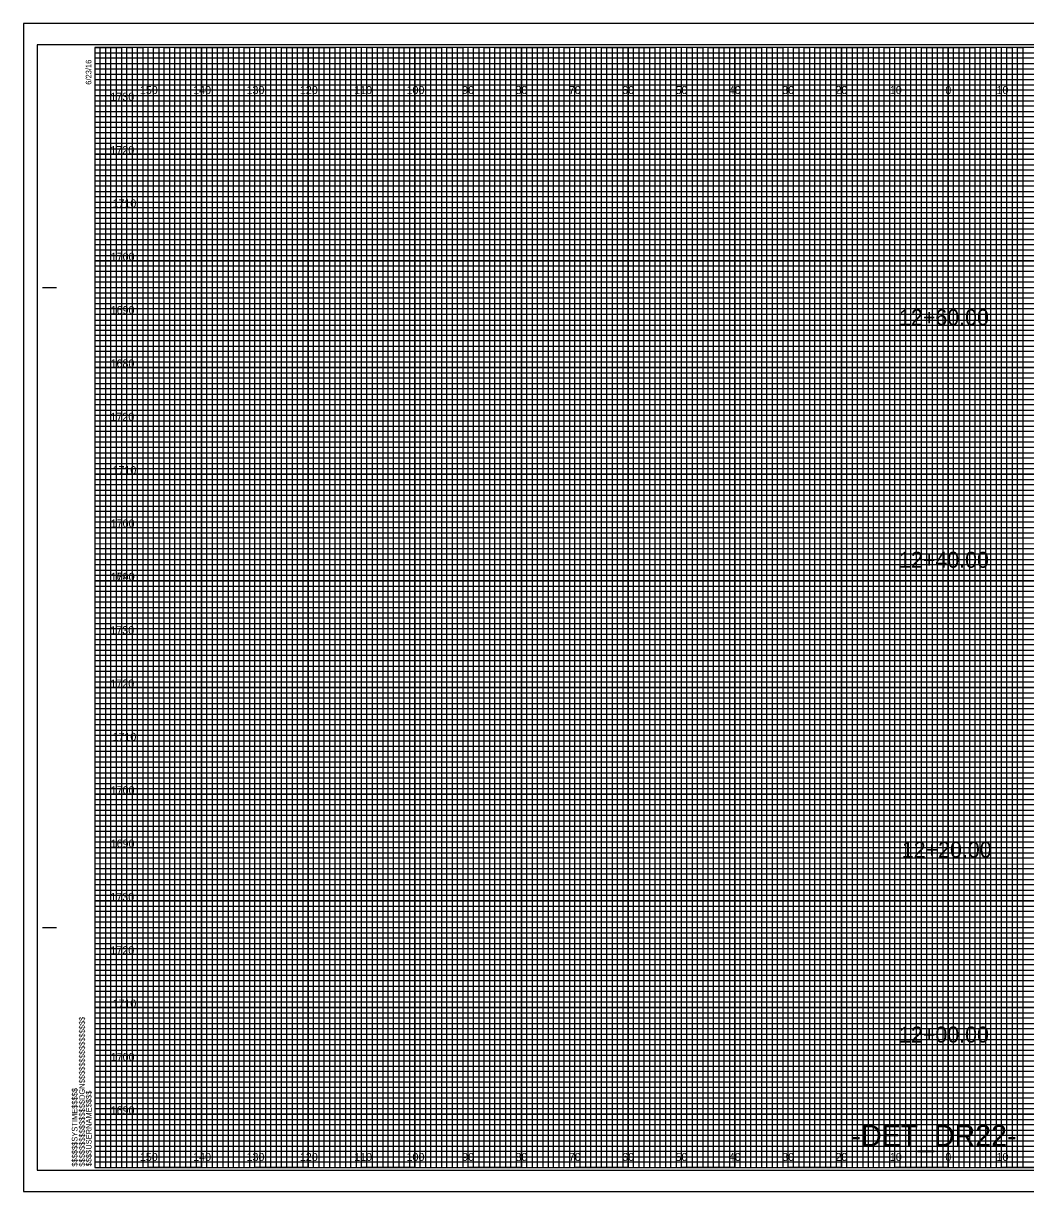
# Model space of a CAD drawing. Extents: x -13 to 323, y -5 to 1314.
# Drawn here: x -13.4 to 174.5, y 435.5 to 654.5 of the extents above; entities that cross this region are included whole.
import ezdxf

# ---------------------------------------------------------------- set-up
doc = ezdxf.new("R2010")
doc.units = 0
for name, color, linetype in [('Prop Horizontal Alignment', 7, 'Continuous'), ('Prop XS Alignment Label', 7, 'Continuous'), ('Raster_Level_0', 7, 'Continuous'), ('Scratch_Level_3', 7, 'Continuous'), ('Sheet Cross Section CELL', 7, 'Continuous'), ('Sheet Cross Section Grid Major CELL', 7, 'Continuous'), ('Sheet Cross Section Grid Middle CELL', 7, 'Continuous'), ('Sheet Cross Section Grid Minor 1 CELL', 7, 'Continuous'), ('Sheet Cross Section Grid Minor 2 CELL', 7, 'Continuous'), ('Sheet Cutting Line CELL', 7, 'Continuous'), ('Sheet DOT Grid CELL', 7, 'Continuous'), ('Sheet Plot Border Inside CELL', 7, 'Continuous'), ('Sheet Plot Border Outside CELL', 7, 'Continuous')]:
    doc.layers.add(name, color=color, linetype=linetype)

msp = doc.modelspace()

# ---------------------------------------------------------------- linework, layer by layer
at = {"layer": 'Sheet Cross Section CELL'}
for p, q in [((-9.8, 605), (-7.3, 605)), ((-9.7, 605), (-7.2, 605)), ((-9.8, 485), (-7.3, 485)), ((-9.7, 485), (-7.2, 485)), ((0, 440), (0, 440)), ((0, 440), (0, 440)), ((0, 440), (0, 440)), ((0, 440), (0, 440)), ((0, 440), (0, 440)), ((0, 440), (0, 440)), ((0, 440), (0, 440))]:
    msp.add_line(p, q, dxfattribs=at)
msp.add_lwpolyline([(320, 650), (0, 650), (0, 440), (320, 440)], close=True, dxfattribs=at)
at = {"layer": 'Sheet Cross Section Grid Major CELL'}
for p, q in [((10, 650), (0, 650)), ((10, 440), (10, 650)), ((30, 650), (20, 650)), ((20, 650), (20, 440)), ((30, 440), (30, 650)), ((50, 650), (40, 650)), ((40, 650), (40, 440)), ((50, 440), (50, 650)), ((70, 650), (60, 650)), ((60, 650), (60, 440)), ((70, 440), (70, 650)), ((90, 650), (80, 650)), ((80, 650), (80, 440)), ((90, 440), (90, 650)), ((110, 650), (100, 650)), ((100, 650), (100, 440)), ((110, 440), (110, 650)), ((130, 650), (120, 650)), ((120, 650), (120, 440)), ((130, 440), (130, 650)), ((150, 650), (140, 650)), ((140, 650), (140, 440)), ((150, 440), (150, 650)), ((170, 650), (160, 650)), ((160, 650), (160, 440)), ((170, 440), (170, 650)), ((20, 440), (10, 440)), ((40, 440), (30, 440)), ((60, 440), (50, 440)), ((80, 440), (70, 440)), ((100, 440), (90, 440)), ((120, 440), (110, 440)), ((140, 440), (130, 440)), ((160, 440), (150, 440)), ((180, 440), (170, 440))]:
    msp.add_line(p, q, dxfattribs=at)
for points in [[(0, 640), (320, 640), (320, 630), (0, 630)], [(0, 620), (320, 620), (320, 610), (0, 610)], [(0, 600), (320, 600), (320, 590), (0, 590)], [(0, 580), (320, 580), (320, 570), (0, 570)], [(0, 560), (320, 560), (320, 550), (0, 550)], [(0, 540), (320, 540), (320, 530), (0, 530)], [(0, 520), (320, 520), (320, 510), (0, 510)], [(0, 500), (320, 500), (320, 490), (0, 490)], [(0, 480), (320, 480), (320, 470), (0, 470)], [(0, 460), (320, 460), (320, 450), (0, 450)]]:
    msp.add_lwpolyline(points, dxfattribs=at)
at = {"layer": 'Sheet Cross Section Grid Middle CELL'}
for points in [[(0, 650), (5, 650), (5, 440), (15, 440), (15, 650), (25, 650), (25, 440), (35, 440), (35, 650), (45, 650), (45, 440), (55, 440), (55, 650), (65, 650), (65, 440), (75, 440), (75, 650), (85, 650), (85, 440), (95, 440), (95, 650), (105, 650), (105, 440), (115, 440), (115, 650), (125, 650), (125, 440), (135, 440), (135, 650), (145, 650), (145, 440), (155, 440), (155, 650), (165, 650), (165, 440), (175, 440)], [(0, 645), (275, 645)], [(0, 625), (320, 625), (320, 635), (0, 635)], [(0, 605), (320, 605), (320, 615), (0, 615)], [(0, 585), (320, 585), (320, 595), (0, 595)], [(0, 565), (320, 565), (320, 575), (0, 575)], [(0, 545), (320, 545), (320, 555), (0, 555)], [(0, 525), (320, 525), (320, 535), (0, 535)], [(0, 505), (320, 505), (320, 515), (0, 515)], [(0, 485), (320, 485), (320, 495), (0, 495)], [(0, 465), (320, 465), (320, 475), (0, 475)], [(0, 445), (320, 445), (320, 455), (0, 455)]]:
    msp.add_lwpolyline(points, dxfattribs=at)
at = {"layer": 'Sheet Cross Section Grid Minor 1 CELL'}
for p, q in [((0, 649), (260, 649)), ((260, 647.98), (0, 647.98)), ((0, 647.98), (0, 647)), ((0, 647), (260, 647)), ((260, 645.89), (0, 645.89)), ((0, 645.89), (0, 644)), ((0, 644), (320, 644))]:
    msp.add_line(p, q, dxfattribs=at)
for points in [[(0, 643), (270, 643), (320, 643), (320, 642), (0, 642)], [(0, 641), (320, 641), (320, 639), (0, 639)], [(0, 638), (320, 638), (320, 637), (0, 636.98)], [(0, 636), (320, 636), (320, 634), (0, 634)], [(0, 633), (320, 633), (320, 632), (0, 632)], [(0, 631), (320, 631), (320, 629), (0, 629)], [(0, 628), (320, 628), (320, 627), (0, 627)], [(0, 626), (320, 626), (320, 624), (0, 624)], [(0, 623), (320, 623), (320, 622), (0, 622)], [(0, 621), (320, 621), (320, 619), (0, 619)], [(0, 618), (320, 618), (320, 617), (0, 617)], [(0, 616), (320, 616), (320, 613.95), (320, 613), (320, 612), (0, 612)], [(0, 614), (320, 614), (320, 613), (0, 613)], [(0, 611), (320, 611), (320, 609), (0, 609.03)], [(0, 609.03), (320, 609), (320, 608), (0, 608)], [(0, 607), (320, 607), (320, 606), (0, 606)], [(0, 604), (320, 604), (320, 603), (0, 603)], [(0, 602), (320, 602), (320, 601), (0, 601)], [(-0.07, 598.89), (320, 598.89), (320, 597.88), (-0.07, 597.88)], [(0, 597), (320, 597), (320, 596), (0, 596)], [(0, 594), (320, 594), (320, 593), (0, 593)], [(0, 592), (320, 592), (320, 591), (0, 591)], [(0, 589), (320, 589), (320, 588), (0, 588)], [(0, 587), (320, 587), (320, 586), (0, 586)], [(0, 584), (320, 584), (320, 583), (0, 583)], [(0, 582), (320, 582), (320, 581), (0, 581)], [(0, 579), (320, 579), (319.99, 577.98), (0, 578)], [(0, 577), (320, 577), (320, 576), (0, 576)], [(0, 574), (320, 574), (320, 573), (0, 573)], [(0, 572), (320, 572), (320, 571), (0, 571)], [(0, 569), (320, 569), (320, 568), (0, 568)], [(0, 567), (320, 567), (320, 566), (0, 566)], [(0, 564), (320, 564), (320, 563), (0, 563)], [(0, 562), (320, 562), (320, 561), (0, 561)], [(0, 559), (320, 559), (320, 558), (0, 558)], [(0, 556.99), (320.07, 556.91), (320, 556), (0, 556)], [(0, 554), (320, 554), (320, 553), (0, 553)], [(0, 552), (320, 552), (320, 551), (0, 551)], [(0, 549), (320, 549), (320, 548), (0, 548)], [(0, 547), (320, 547), (320, 546), (0, 546)], [(0, 544), (320, 544), (320, 543), (0, 543)], [(0, 542), (320, 542), (320, 541), (0, 541)], [(0, 539), (320, 539), (320, 538), (0, 538)], [(0, 537), (320, 537), (320, 536), (0, 536)], [(0, 534), (320, 534), (320, 533), (0, 533)], [(0, 532), (320, 532), (320, 531), (0, 531)], [(0, 529), (320, 529), (320, 528), (0, 528)], [(0, 527), (320, 527), (320, 526), (0, 526)], [(0, 524), (320, 524), (320, 523), (0, 523)], [(0, 522), (320, 522), (320, 521), (0, 521)], [(0, 519), (320, 519), (319.99, 517.98), (0, 518)], [(0, 517), (320, 517), (320, 516), (0, 516)], [(0, 514), (320, 514), (320, 513), (0, 513)], [(0, 512), (320, 512), (320, 511), (0, 511)], [(0, 509), (320, 509), (320, 508), (0, 508)], [(0, 507), (320, 507), (320, 506), (0, 506)], [(0, 504), (320, 504), (320, 503), (0, 503)], [(0, 502), (320, 502), (320, 501), (0, 501)], [(0, 499), (320, 499), (320, 498), (0, 498)], [(0, 496.99), (320.07, 496.91), (320, 496), (0, 496)], [(0, 494), (320, 494), (320, 493), (0, 493)], [(0, 492), (320, 492), (320, 491), (0, 491)], [(0, 489), (320, 489), (320, 488), (0, 488)], [(0, 487), (320, 487), (320, 486), (0, 486)], [(0, 484), (320, 484), (320, 483), (0, 483)], [(0, 482), (320, 482), (320, 481), (0, 481)], [(0, 479), (320, 479), (320, 478), (0, 478)], [(0, 477), (320, 477), (320, 476), (0, 476)], [(0, 474), (320, 474), (320, 473), (0, 473)], [(0, 472), (320, 472), (320, 471), (0, 471)], [(0, 469), (320, 469), (320, 468), (0, 468)], [(0, 467), (320, 467), (320, 466), (0, 466)], [(0, 464), (320, 464), (320, 463), (0, 463)], [(0, 462), (320, 462), (320, 461), (0, 461)], [(0, 459), (320, 459), (320, 458), (0, 458)], [(0, 457), (320, 457), (320, 456), (0, 456)], [(0, 454), (320, 454), (320, 453), (0, 453)], [(0, 452), (320, 452), (320, 451), (0, 451)], [(0, 449), (320, 449), (320, 448), (0, 448)], [(0, 447), (320, 447), (320, 446), (0, 446)], [(0, 444), (320, 444), (320, 443), (0, 443)], [(0, 442), (320, 442), (320, 441), (0, 441)]]:
    msp.add_lwpolyline(points, dxfattribs=at)
at = {"layer": 'Sheet Cross Section Grid Minor 2 CELL'}
for points in [[(0, 440), (1, 440), (1, 650), (2, 650), (2, 440)], [(2, 440), (3, 440), (3, 650), (4, 650), (4, 440)], [(5, 440), (6, 440), (6, 650), (7, 650), (7, 440)], [(7, 440), (8, 440), (8, 650), (9, 650), (9, 440)], [(10, 440), (11, 440), (11, 650), (12, 650), (12, 440)], [(12, 440), (13, 440), (13, 650), (14, 650), (14, 440)], [(15, 440), (16, 440), (16, 650), (17, 650), (17, 440)], [(17, 440), (18, 440), (18, 650), (19, 650), (19, 440)], [(20, 440), (21, 440), (21, 650), (22, 650), (22, 440)], [(22, 440), (23, 440), (23, 650), (24, 650), (24, 440)], [(25, 440), (26, 440), (26, 650), (27, 650), (27, 440)], [(27, 440), (28, 440), (28, 650), (29, 650), (29, 440)], [(30, 440), (31, 440), (31, 650), (32, 650), (32, 440)], [(32, 440), (33, 440), (33, 650), (34, 650), (34, 440)], [(35, 440), (36, 440), (36, 650), (37, 650), (37, 440)], [(37, 440), (38, 440), (38, 650), (39, 650), (39, 440)], [(40, 440), (41, 440), (41, 650), (42, 650), (42, 440)], [(42, 440), (43, 440), (43, 650), (44, 650), (44, 440)], [(45, 440), (46, 440), (46, 650), (47, 650), (47, 440)], [(47, 440), (48, 440), (48, 650), (49, 650), (49, 440)], [(50, 440), (51, 440), (51, 650), (52, 650), (52, 440)], [(52, 440), (53, 440), (53, 650), (54, 650), (54, 440)], [(55, 440), (56, 440), (56, 650), (57, 650), (57, 440)], [(57, 440), (58, 440), (58, 650), (59, 650), (59, 440)], [(60, 440), (61, 440), (61, 650), (62, 650), (62, 440)], [(62, 440), (63, 440), (63, 650), (64, 650), (64, 440)], [(65, 440), (66, 440), (66, 650), (67, 650), (67, 440)], [(67, 440), (68, 440), (68, 650), (69, 650), (69, 440)], [(70, 440), (71, 440), (71, 650), (72, 650), (72, 440)], [(72, 440), (73, 440), (73, 650), (74, 650), (74, 440)], [(75, 440), (76, 440), (76, 650), (77, 650), (77, 440)], [(77, 440), (78, 440), (78, 650), (79, 650), (79, 440)], [(80, 440), (81, 440), (81, 650), (82, 650), (82, 440)], [(82, 440), (83, 440), (83, 650), (84, 650), (84, 440)], [(85, 440), (86, 440), (86, 650), (87, 650), (87, 440)], [(87, 440), (88, 440), (88, 650), (89, 650), (89, 440)], [(90, 440), (91, 440), (91, 650), (92, 650), (92, 440)], [(92, 440), (93, 440), (93, 650), (94, 650), (94, 440)], [(95, 440), (96, 440), (96, 650), (97, 650), (97, 440)], [(97, 440), (98, 440), (98, 650), (99, 650), (99, 440)], [(100, 440), (101, 440), (101, 650), (102, 650), (102, 440)], [(102, 440), (103, 440), (103, 650), (104, 650), (104, 440)], [(105, 440), (106, 440), (106, 650), (107, 650), (107, 440)], [(107, 440), (108, 440), (108, 650), (109, 650), (109, 440)], [(110, 440), (111, 440), (111, 650), (112, 650), (112, 440)], [(112, 440), (113, 440), (113, 650), (114, 650), (114, 440)], [(115, 440), (116, 440), (116, 650), (117, 650), (117, 440)], [(117, 440), (118, 440), (118, 650), (119, 650), (119, 440)], [(120, 440), (121, 440), (121, 650), (122, 650), (122, 440)], [(122, 440), (123, 440), (123, 650), (124, 650), (124, 440)], [(125, 440), (126, 440), (126, 650), (127, 650), (127, 440)], [(127, 440), (128, 440), (128, 650), (129, 650), (129, 440)], [(130, 440), (131, 440), (131, 650), (132, 650), (132, 440)], [(132, 440), (133, 440), (133, 650), (134, 650), (134, 440)], [(135, 440), (136, 440), (136, 650), (137, 650), (137, 440)], [(137, 440), (138, 440), (138, 650), (139, 650), (139, 440)], [(140, 440), (141, 440), (141, 650), (142, 650), (142, 440)], [(142, 440), (143, 440), (143, 650), (144, 650), (144, 440)], [(145, 440), (146, 440), (146, 650), (147, 650), (147, 440)], [(147, 440), (148, 440), (148, 650), (149, 650), (149, 440)], [(150, 440), (151, 440), (151, 650), (152, 650), (152, 440)], [(152, 440), (153, 440), (153, 650), (154, 650), (154, 440)], [(155, 440), (156, 440), (156, 650), (157, 650), (157, 440)], [(157, 440), (158, 440), (158, 650), (159, 650), (159, 440)], [(160, 440), (161, 440), (161, 650), (162, 650), (162, 440)], [(162, 440), (163, 440), (163, 650), (164, 650), (164, 440)], [(165, 440), (166, 440), (166, 650), (167, 650), (167, 440)], [(167, 440), (168, 440), (168, 650), (169, 650), (169, 440)], [(170, 440), (171, 440), (171, 650), (172, 650), (172, 440)], [(172, 440), (173, 440), (173, 650), (174, 650), (174, 440)]]:
    msp.add_lwpolyline(points, dxfattribs=at)
at = {"layer": 'Sheet Cutting Line CELL'}
for p, q in [((323.3, 654.5), (-13.4, 654.5)), ((-13.4, 654.5), (-13.4, 435.5)), ((-13.4, 435.5), (323.3, 435.5))]:
    msp.add_line(p, q, dxfattribs=at)
at = {"layer": 'Sheet DOT Grid CELL'}
for p, q in [((10, 440), (10, 650)), ((20, 440), (20, 650)), ((30, 440), (30, 650)), ((40, 440), (40, 650)), ((50, 440), (50, 650)), ((60, 440), (60, 650)), ((70, 440), (70, 650)), ((80, 440), (80, 650)), ((90, 440), (90, 650)), ((100, 440), (100, 650)), ((110, 440), (110, 650)), ((120, 440), (120, 650)), ((130, 440), (130, 650)), ((140, 440), (140, 650)), ((150, 440), (150, 650)), ((160, 440), (160, 650)), ((170, 440), (170, 650)), ((0, 640), (320, 640)), ((0, 630), (320, 630)), ((0, 620), (320, 620)), ((0, 610), (320, 610)), ((0, 600), (320, 600)), ((0, 590), (320, 590)), ((0, 580), (320, 580)), ((0, 570), (320, 570)), ((0, 560), (320, 560)), ((0, 550), (320, 550)), ((0, 540), (320, 540)), ((0, 530), (320, 530)), ((0, 520), (320, 520)), ((0, 510), (320, 510)), ((0, 500), (320, 500)), ((0, 490), (320, 490)), ((0, 480), (320, 480)), ((0, 470), (320, 470)), ((0, 460), (320, 460)), ((0, 450), (320, 450))]:
    msp.add_line(p, q, dxfattribs=at)
at = {"layer": 'Sheet Plot Border Inside CELL'}
msp.add_lwpolyline([(-10.8, 439.5), (322.4, 439.5), (322.4, 650.5), (-10.8, 650.5)], close=True, dxfattribs=at)
at = {"layer": 'Sheet Plot Border Outside CELL'}
msp.add_lwpolyline([(-13.4, 435.5), (323.3, 435.5), (323.3, 654.5), (-13.4, 654.5)], close=True, dxfattribs=at)

# ---------------------------------------------------------------- texts
at = {"layer": 'Prop Horizontal Alignment'}
for s, p in [('12+60.00', (150.77, 597.9)), ('12+40.00', (150.77, 552.45)), ('12+20.00', (151.28, 498.11)), ('12+00.00', (150.77, 463.45))]:
    msp.add_text(s, height=3, dxfattribs=at).set_placement(p)
at = {"layer": 'Prop XS Alignment Label'}
msp.add_text('-DET_DR22-', height=4, dxfattribs=at).set_placement((141.87, 444))
at = {"layer": 'Raster_Level_0'}
for s, p in [('150', (8.44, 641.25)), ('140', (18.44, 641.25)), ('130', (28.44, 641.25)), ('120', (38.44, 641.25)), ('110', (48.62, 641.25)), ('100', (58.44, 641.25)), ('90', (68.86, 641.25)), ('80', (78.86, 641.25)), ('70', (88.86, 641.25)), ('60', (98.86, 641.25)), ('50', (108.86, 641.25)), ('40', (118.86, 641.25)), ('30', (128.86, 641.25)), ('20', (138.86, 641.25)), ('10', (149.04, 641.25)), ('0', (159.45, 641.25)), ('0', (159.45, 641.25)), ('10', (169.04, 641.25)), ('150', (8.44, 441.25)), ('140', (18.44, 441.25)), ('130', (28.44, 441.25)), ('120', (38.44, 441.25)), ('110', (48.62, 441.25)), ('100', (58.44, 441.25)), ('90', (68.86, 441.25)), ('80', (78.86, 441.25)), ('70', (88.86, 441.25)), ('60', (98.86, 441.25)), ('50', (108.86, 441.25)), ('40', (118.86, 441.25)), ('30', (128.86, 441.25)), ('20', (138.86, 441.25)), ('10', (149.04, 441.25)), ('0', (159.45, 441.25)), ('0', (159.45, 441.25)), ('10', (169.04, 441.25))]:
    msp.add_text(s, height=1.5, dxfattribs=at).set_placement(p)
at = {"layer": 'Scratch_Level_3'}
for s, p in [('1730', (2.92, 640)), ('1720', (2.93, 630)), ('1710', (3.31, 620)), ('1700', (2.98, 610)), ('1690', (2.97, 600)), ('1680', (2.95, 590)), ('1720', (2.93, 580)), ('1710', (3.31, 570)), ('1700', (2.98, 560)), ('1690', (2.97, 550)), ('1740', (3, 550)), ('1730', (2.92, 540)), ('1720', (2.93, 530)), ('1710', (3.31, 520)), ('1700', (2.98, 510)), ('1690', (2.97, 500)), ('1730', (2.92, 490)), ('1720', (2.93, 480)), ('1710', (3.31, 470)), ('1700', (2.98, 460)), ('1690', (2.97, 450))]:
    msp.add_text(s, height=1.5, dxfattribs=at).set_placement(p)
at = {"layer": 'Sheet Cross Section CELL'}
for s, p in [('6/23/16', (-0.65, 643)), ('$$$$$$$$$$$$$$$$DGN$$$$$$$$$$$$$$$$', (-1.88, 440.18)), ('$$$$$$SYSTIME$$$$$', (-3.26, 440.18)), ('$$$$USERNAME$$$$', (-0.62, 440.23))]:
    msp.add_text(s, height=1.05, rotation=90, dxfattribs=at).set_placement(p)

doc.saveas('drawing.dxf')
